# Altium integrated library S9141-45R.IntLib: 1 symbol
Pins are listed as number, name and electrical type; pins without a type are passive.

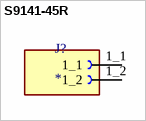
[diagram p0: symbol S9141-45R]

## S9141-45R
designator J?
MP: S9141-45R
footprint HARWIN_S9141-45R
pins: 1_1, 1_2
